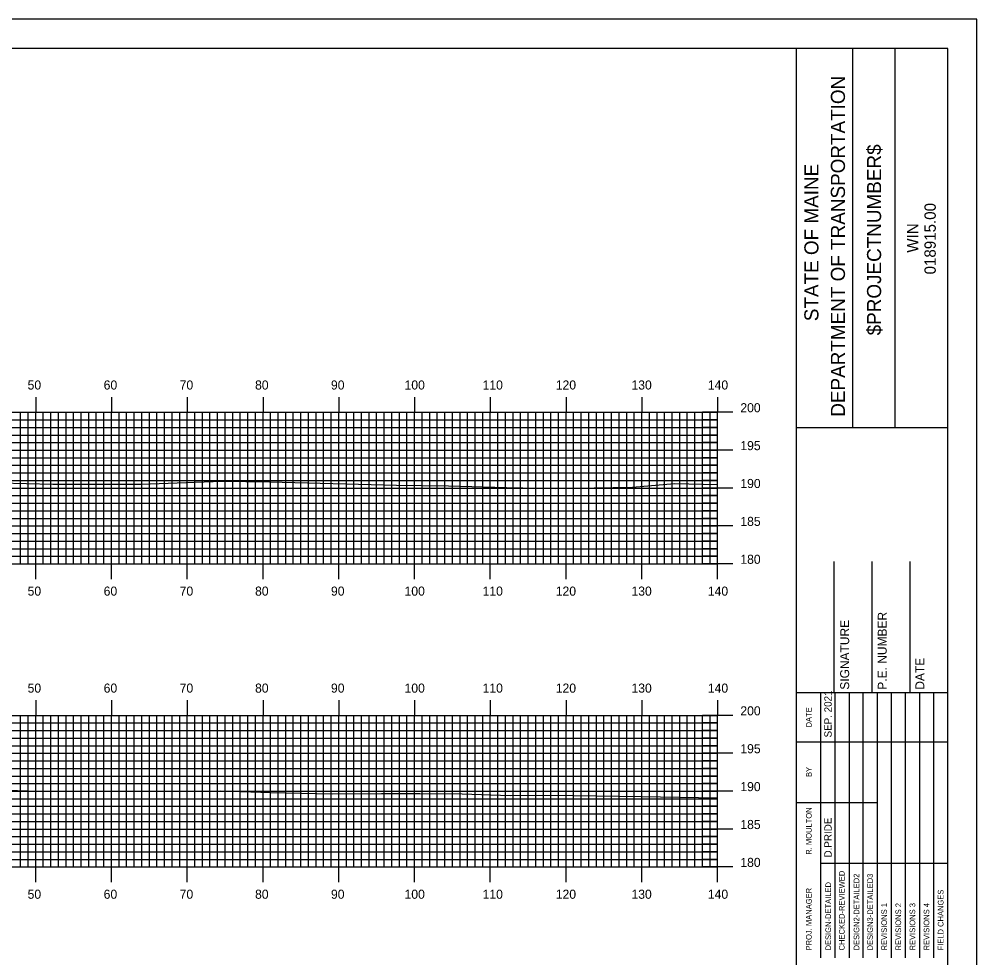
# Model space of a CAD drawing. Extents: x 1798388 to 1798731, y 442591 to 442811.
# Drawn here: x 1798601.3 to 1798727.7, y 442686.7 to 442810.5 of the extents above; entities that cross this region are included whole.
import ezdxf

# ---------------------------------------------------------------- set-up
doc = ezdxf.new("R2010")
doc.units = 0
for name, color, linetype in [('BORDER', 7, 'Continuous'), ('H_V ANNOTATION', 7, 'Continuous'), ('MAJOR', 7, 'Continuous'), ('MINOR', 7, 'Continuous'), ('PLOT BOUNDARY', 7, 'Continuous'), ('S_Roadway_Centerline', 7, 'Continuous')]:
    doc.layers.add(name, color=color, linetype=linetype)

msp = doc.modelspace()

# ---------------------------------------------------------------- linework, layer by layer
at = {"layer": 'BORDER'}
for p, q in [((1798703.87, 442596.67), (1798703.87, 442806.67)), ((1798711.33, 442756.66), (1798711.33, 442806.66)), ((1798716.92, 442756.66), (1798716.92, 442806.66)), ((1798703.87, 442756.65), (1798723.87, 442756.65)), ((1798708.87, 442721.67), (1798708.87, 442738.97)), ((1798713.87, 442721.67), (1798713.87, 442738.97)), ((1798718.87, 442721.67), (1798718.87, 442738.97)), ((1798703.87, 442721.67), (1798723.87, 442721.67))]:
    msp.add_line(p, q, dxfattribs=at)
msp.add_lwpolyline([(1798403.87, 442596.67), (1798723.87, 442596.67), (1798723.87, 442806.67), (1798403.87, 442806.67)], close=True, dxfattribs=at)
for points in [[(1798707.1, 442715.17), (1798707.1, 442721.67)], [(1798708.97, 442686.68), (1798708.97, 442721.67)], [(1798710.83, 442721.67), (1798710.83, 442686.68)], [(1798712.69, 442686.68), (1798712.69, 442721.67)], [(1798714.56, 442686.68), (1798714.56, 442721.67)], [(1798716.42, 442686.68), (1798716.42, 442721.67)], [(1798718.28, 442686.68), (1798718.28, 442721.67)], [(1798720.15, 442686.68), (1798720.15, 442721.67)], [(1798722.01, 442686.68), (1798722.01, 442721.67)], [(1798707.1, 442686.68), (1798707.1, 442720.26)], [(1798703.87, 442715.17), (1798723.87, 442715.17)], [(1798703.87, 442707.17), (1798707.1, 442707.17)], [(1798707.1, 442707.17), (1798714.55, 442707.17)], [(1798707.1, 442699.17), (1798723.87, 442699.17)]]:
    msp.add_lwpolyline(points, dxfattribs=at)
at = {"layer": 'MAJOR'}
for p, q in [((1798603.47, 442760.67), (1798603.47, 442758.67)), ((1798613.47, 442760.67), (1798613.47, 442758.67)), ((1798623.47, 442760.67), (1798623.47, 442758.67)), ((1798633.47, 442760.67), (1798633.47, 442758.67)), ((1798643.47, 442760.67), (1798643.47, 442758.67)), ((1798653.47, 442760.67), (1798653.47, 442758.67)), ((1798663.47, 442760.67), (1798663.47, 442758.67)), ((1798673.47, 442760.67), (1798673.47, 442758.67)), ((1798683.47, 442760.67), (1798683.47, 442758.67)), ((1798693.47, 442760.67), (1798693.47, 442758.67)), ((1798413.47, 442758.67), (1798693.47, 442758.67)), ((1798413.47, 442758.67), (1798693.47, 442758.67)), ((1798603.47, 442738.67), (1798603.47, 442758.67)), ((1798613.47, 442738.67), (1798613.47, 442758.67)), ((1798623.47, 442738.67), (1798623.47, 442758.67)), ((1798633.47, 442738.67), (1798633.47, 442758.67)), ((1798643.47, 442738.67), (1798643.47, 442758.67)), ((1798653.47, 442738.67), (1798653.47, 442758.67)), ((1798663.47, 442738.67), (1798663.47, 442758.67)), ((1798673.47, 442738.67), (1798673.47, 442758.67)), ((1798683.47, 442738.67), (1798683.47, 442758.67)), ((1798695.47, 442758.67), (1798691.47, 442758.67)), ((1798693.47, 442738.67), (1798693.47, 442758.67)), ((1798693.47, 442738.67), (1798693.47, 442758.67)), ((1798413.47, 442753.67), (1798693.47, 442753.67)), ((1798695.47, 442753.67), (1798691.47, 442753.67)), ((1798413.47, 442748.67), (1798693.47, 442748.67)), ((1798695.47, 442748.67), (1798691.47, 442748.67)), ((1798413.47, 442743.67), (1798693.47, 442743.67)), ((1798695.47, 442743.67), (1798691.47, 442743.67)), ((1798413.47, 442738.67), (1798693.47, 442738.67)), ((1798413.47, 442738.67), (1798693.47, 442738.67)), ((1798603.47, 442736.66), (1798603.47, 442738.67)), ((1798613.47, 442736.66), (1798613.47, 442738.67)), ((1798623.47, 442736.66), (1798623.47, 442738.67)), ((1798633.47, 442736.66), (1798633.47, 442738.67)), ((1798643.47, 442736.66), (1798643.47, 442738.67)), ((1798653.47, 442736.66), (1798653.47, 442738.67)), ((1798663.47, 442736.66), (1798663.47, 442738.67)), ((1798673.47, 442736.66), (1798673.47, 442738.67)), ((1798683.47, 442736.66), (1798683.47, 442738.67)), ((1798695.47, 442738.67), (1798691.47, 442738.67)), ((1798693.47, 442736.66), (1798693.47, 442738.67)), ((1798603.47, 442720.67), (1798603.47, 442718.67)), ((1798613.47, 442720.67), (1798613.47, 442718.67)), ((1798623.47, 442720.67), (1798623.47, 442718.67)), ((1798633.47, 442720.67), (1798633.47, 442718.67)), ((1798643.47, 442720.67), (1798643.47, 442718.67)), ((1798653.47, 442720.67), (1798653.47, 442718.67)), ((1798663.47, 442720.67), (1798663.47, 442718.67)), ((1798673.47, 442720.67), (1798673.47, 442718.67)), ((1798683.47, 442720.67), (1798683.47, 442718.67)), ((1798693.47, 442720.67), (1798693.47, 442718.67)), ((1798413.47, 442718.67), (1798693.47, 442718.67)), ((1798413.47, 442718.67), (1798693.47, 442718.67)), ((1798603.47, 442698.67), (1798603.47, 442718.67)), ((1798613.47, 442698.67), (1798613.47, 442718.67)), ((1798623.47, 442698.67), (1798623.47, 442718.67)), ((1798633.47, 442698.67), (1798633.47, 442718.67)), ((1798643.47, 442698.67), (1798643.47, 442718.67)), ((1798653.47, 442698.67), (1798653.47, 442718.67)), ((1798663.47, 442698.67), (1798663.47, 442718.67)), ((1798673.47, 442698.67), (1798673.47, 442718.67)), ((1798683.47, 442698.67), (1798683.47, 442718.67)), ((1798695.47, 442718.67), (1798691.47, 442718.67)), ((1798693.47, 442698.67), (1798693.47, 442718.67)), ((1798693.47, 442698.67), (1798693.47, 442718.67)), ((1798413.47, 442713.67), (1798693.47, 442713.67)), ((1798695.47, 442713.67), (1798691.47, 442713.67)), ((1798413.47, 442708.67), (1798693.47, 442708.67)), ((1798695.47, 442708.67), (1798691.47, 442708.67)), ((1798413.47, 442703.67), (1798693.47, 442703.67)), ((1798695.47, 442703.67), (1798691.47, 442703.67)), ((1798413.47, 442698.67), (1798693.47, 442698.67)), ((1798413.47, 442698.67), (1798693.47, 442698.67)), ((1798603.47, 442696.66), (1798603.47, 442698.67)), ((1798613.47, 442696.66), (1798613.47, 442698.67)), ((1798623.47, 442696.66), (1798623.47, 442698.67)), ((1798633.47, 442696.66), (1798633.47, 442698.67)), ((1798643.47, 442696.66), (1798643.47, 442698.67)), ((1798653.47, 442696.66), (1798653.47, 442698.67)), ((1798663.47, 442696.66), (1798663.47, 442698.67)), ((1798673.47, 442696.66), (1798673.47, 442698.67)), ((1798683.47, 442696.66), (1798683.47, 442698.67)), ((1798695.47, 442698.67), (1798691.47, 442698.67)), ((1798693.47, 442696.66), (1798693.47, 442698.67))]:
    msp.add_line(p, q, dxfattribs=at)
at = {"layer": 'MINOR'}
for p, q in [((1798601.47, 442738.67), (1798601.47, 442758.67)), ((1798602.47, 442738.67), (1798602.47, 442758.67)), ((1798604.47, 442738.67), (1798604.47, 442758.67)), ((1798605.47, 442738.67), (1798605.47, 442758.67)), ((1798606.47, 442738.67), (1798606.47, 442758.67)), ((1798607.47, 442738.67), (1798607.47, 442758.67)), ((1798608.47, 442738.67), (1798608.47, 442758.67)), ((1798609.47, 442738.67), (1798609.47, 442758.67)), ((1798610.47, 442738.67), (1798610.47, 442758.67)), ((1798611.47, 442738.67), (1798611.47, 442758.67)), ((1798612.47, 442738.67), (1798612.47, 442758.67)), ((1798614.47, 442738.67), (1798614.47, 442758.67)), ((1798615.47, 442738.67), (1798615.47, 442758.67)), ((1798616.47, 442738.67), (1798616.47, 442758.67)), ((1798617.47, 442738.67), (1798617.47, 442758.67)), ((1798618.47, 442738.67), (1798618.47, 442758.67)), ((1798619.47, 442738.67), (1798619.47, 442758.67)), ((1798620.47, 442738.67), (1798620.47, 442758.67)), ((1798621.47, 442738.67), (1798621.47, 442758.67)), ((1798622.47, 442738.67), (1798622.47, 442758.67)), ((1798624.47, 442738.67), (1798624.47, 442758.67)), ((1798625.47, 442738.67), (1798625.47, 442758.67)), ((1798626.47, 442738.67), (1798626.47, 442758.67)), ((1798627.47, 442738.67), (1798627.47, 442758.67)), ((1798628.47, 442738.67), (1798628.47, 442758.67)), ((1798629.47, 442738.67), (1798629.47, 442758.67)), ((1798630.47, 442738.67), (1798630.47, 442758.67)), ((1798631.47, 442738.67), (1798631.47, 442758.67)), ((1798632.47, 442738.67), (1798632.47, 442758.67)), ((1798634.47, 442738.67), (1798634.47, 442758.67)), ((1798635.47, 442738.67), (1798635.47, 442758.67)), ((1798636.47, 442738.67), (1798636.47, 442758.67)), ((1798637.47, 442738.67), (1798637.47, 442758.67)), ((1798638.47, 442738.67), (1798638.47, 442758.67)), ((1798639.47, 442738.67), (1798639.47, 442758.67)), ((1798640.47, 442738.67), (1798640.47, 442758.67)), ((1798641.47, 442738.67), (1798641.47, 442758.67)), ((1798642.47, 442738.67), (1798642.47, 442758.67)), ((1798644.47, 442738.67), (1798644.47, 442758.67)), ((1798645.47, 442738.67), (1798645.47, 442758.67)), ((1798646.47, 442738.67), (1798646.47, 442758.67)), ((1798647.47, 442738.67), (1798647.47, 442758.67)), ((1798648.47, 442738.67), (1798648.47, 442758.67)), ((1798649.47, 442738.67), (1798649.47, 442758.67)), ((1798650.47, 442738.67), (1798650.47, 442758.67)), ((1798651.47, 442738.67), (1798651.47, 442758.67)), ((1798652.47, 442738.67), (1798652.47, 442758.67)), ((1798654.47, 442738.67), (1798654.47, 442758.67)), ((1798655.47, 442738.67), (1798655.47, 442758.67)), ((1798656.47, 442738.67), (1798656.47, 442758.67)), ((1798657.47, 442738.67), (1798657.47, 442758.67)), ((1798658.47, 442738.67), (1798658.47, 442758.67)), ((1798659.47, 442738.67), (1798659.47, 442758.67)), ((1798660.47, 442738.67), (1798660.47, 442758.67)), ((1798661.47, 442738.67), (1798661.47, 442758.67)), ((1798662.47, 442738.67), (1798662.47, 442758.67)), ((1798664.47, 442738.67), (1798664.47, 442758.67)), ((1798665.47, 442738.67), (1798665.47, 442758.67)), ((1798666.47, 442738.67), (1798666.47, 442758.67)), ((1798667.47, 442738.67), (1798667.47, 442758.67)), ((1798668.47, 442738.67), (1798668.47, 442758.67)), ((1798669.47, 442738.67), (1798669.47, 442758.67)), ((1798670.47, 442738.67), (1798670.47, 442758.67)), ((1798671.47, 442738.67), (1798671.47, 442758.67)), ((1798672.47, 442738.67), (1798672.47, 442758.67)), ((1798674.47, 442738.67), (1798674.47, 442758.67)), ((1798675.47, 442738.67), (1798675.47, 442758.67)), ((1798676.47, 442738.67), (1798676.47, 442758.67)), ((1798677.47, 442738.67), (1798677.47, 442758.67)), ((1798678.47, 442738.67), (1798678.47, 442758.67)), ((1798679.47, 442738.67), (1798679.47, 442758.67)), ((1798680.47, 442738.67), (1798680.47, 442758.67)), ((1798681.47, 442738.67), (1798681.47, 442758.67)), ((1798682.47, 442738.67), (1798682.47, 442758.67)), ((1798684.47, 442738.67), (1798684.47, 442758.67)), ((1798685.47, 442738.67), (1798685.47, 442758.67)), ((1798686.47, 442738.67), (1798686.47, 442758.67)), ((1798687.47, 442738.67), (1798687.47, 442758.67)), ((1798688.47, 442738.67), (1798688.47, 442758.67)), ((1798689.47, 442738.67), (1798689.47, 442758.67)), ((1798690.47, 442738.67), (1798690.47, 442758.67)), ((1798691.47, 442738.67), (1798691.47, 442758.67)), ((1798692.47, 442738.67), (1798692.47, 442758.67)), ((1798413.47, 442757.67), (1798693.47, 442757.67)), ((1798413.47, 442756.67), (1798693.47, 442756.67)), ((1798693.47, 442757.67), (1798691.47, 442757.67)), ((1798693.47, 442756.67), (1798691.47, 442756.67)), ((1798413.47, 442755.67), (1798693.47, 442755.67)), ((1798693.47, 442755.67), (1798691.47, 442755.67)), ((1798413.47, 442754.67), (1798693.47, 442754.67)), ((1798693.47, 442754.67), (1798691.47, 442754.67)), ((1798413.47, 442752.67), (1798693.47, 442752.67)), ((1798693.47, 442752.67), (1798691.47, 442752.67)), ((1798413.47, 442751.67), (1798693.47, 442751.67)), ((1798693.47, 442751.67), (1798691.47, 442751.67)), ((1798413.47, 442750.67), (1798693.47, 442750.67)), ((1798693.47, 442750.67), (1798691.47, 442750.67)), ((1798413.47, 442749.67), (1798693.47, 442749.67)), ((1798693.47, 442749.67), (1798691.47, 442749.67)), ((1798413.47, 442747.67), (1798693.47, 442747.67)), ((1798693.47, 442747.67), (1798691.47, 442747.67)), ((1798413.47, 442746.67), (1798693.47, 442746.67)), ((1798693.47, 442746.67), (1798691.47, 442746.67)), ((1798413.47, 442745.67), (1798693.47, 442745.67)), ((1798693.47, 442745.67), (1798691.47, 442745.67)), ((1798413.47, 442744.67), (1798693.47, 442744.67)), ((1798693.47, 442744.67), (1798691.47, 442744.67)), ((1798413.47, 442742.67), (1798693.47, 442742.67)), ((1798693.47, 442742.67), (1798691.47, 442742.67)), ((1798413.47, 442741.67), (1798693.47, 442741.67)), ((1798693.47, 442741.67), (1798691.47, 442741.67)), ((1798413.47, 442740.67), (1798693.47, 442740.67)), ((1798693.47, 442740.67), (1798691.47, 442740.67)), ((1798413.47, 442739.67), (1798693.47, 442739.67)), ((1798693.47, 442739.67), (1798691.47, 442739.67)), ((1798601.47, 442698.67), (1798601.47, 442718.67)), ((1798602.47, 442698.67), (1798602.47, 442718.67)), ((1798604.47, 442698.67), (1798604.47, 442718.67)), ((1798605.47, 442698.67), (1798605.47, 442718.67)), ((1798606.47, 442698.67), (1798606.47, 442718.67)), ((1798607.47, 442698.67), (1798607.47, 442718.67)), ((1798608.47, 442698.67), (1798608.47, 442718.67)), ((1798609.47, 442698.67), (1798609.47, 442718.67)), ((1798610.47, 442698.67), (1798610.47, 442718.67)), ((1798611.47, 442698.67), (1798611.47, 442718.67)), ((1798612.47, 442698.67), (1798612.47, 442718.67)), ((1798614.47, 442698.67), (1798614.47, 442718.67)), ((1798615.47, 442698.67), (1798615.47, 442718.67)), ((1798616.47, 442698.67), (1798616.47, 442718.67)), ((1798617.47, 442698.67), (1798617.47, 442718.67)), ((1798618.47, 442698.67), (1798618.47, 442718.67)), ((1798619.47, 442698.67), (1798619.47, 442718.67)), ((1798620.47, 442698.67), (1798620.47, 442718.67)), ((1798621.47, 442698.67), (1798621.47, 442718.67)), ((1798622.47, 442698.67), (1798622.47, 442718.67)), ((1798624.47, 442698.67), (1798624.47, 442718.67)), ((1798625.47, 442698.67), (1798625.47, 442718.67)), ((1798626.47, 442698.67), (1798626.47, 442718.67)), ((1798627.47, 442698.67), (1798627.47, 442718.67)), ((1798628.47, 442698.67), (1798628.47, 442718.67)), ((1798629.47, 442698.67), (1798629.47, 442718.67)), ((1798630.47, 442698.67), (1798630.47, 442718.67)), ((1798631.47, 442698.67), (1798631.47, 442718.67)), ((1798632.47, 442698.67), (1798632.47, 442718.67)), ((1798634.47, 442698.67), (1798634.47, 442718.67)), ((1798635.47, 442698.67), (1798635.47, 442718.67)), ((1798636.47, 442698.67), (1798636.47, 442718.67)), ((1798637.47, 442698.67), (1798637.47, 442718.67)), ((1798638.47, 442698.67), (1798638.47, 442718.67)), ((1798639.47, 442698.67), (1798639.47, 442718.67)), ((1798640.47, 442698.67), (1798640.47, 442718.67)), ((1798641.47, 442698.67), (1798641.47, 442718.67)), ((1798642.47, 442698.67), (1798642.47, 442718.67)), ((1798644.47, 442698.67), (1798644.47, 442718.67)), ((1798645.47, 442698.67), (1798645.47, 442718.67)), ((1798646.47, 442698.67), (1798646.47, 442718.67)), ((1798647.47, 442698.67), (1798647.47, 442718.67)), ((1798648.47, 442698.67), (1798648.47, 442718.67)), ((1798649.47, 442698.67), (1798649.47, 442718.67)), ((1798650.47, 442698.67), (1798650.47, 442718.67)), ((1798651.47, 442698.67), (1798651.47, 442718.67)), ((1798652.47, 442698.67), (1798652.47, 442718.67)), ((1798654.47, 442698.67), (1798654.47, 442718.67)), ((1798655.47, 442698.67), (1798655.47, 442718.67)), ((1798656.47, 442698.67), (1798656.47, 442718.67)), ((1798657.47, 442698.67), (1798657.47, 442718.67)), ((1798658.47, 442698.67), (1798658.47, 442718.67)), ((1798659.47, 442698.67), (1798659.47, 442718.67)), ((1798660.47, 442698.67), (1798660.47, 442718.67)), ((1798661.47, 442698.67), (1798661.47, 442718.67)), ((1798662.47, 442698.67), (1798662.47, 442718.67)), ((1798664.47, 442698.67), (1798664.47, 442718.67)), ((1798665.47, 442698.67), (1798665.47, 442718.67)), ((1798666.47, 442698.67), (1798666.47, 442718.67)), ((1798667.47, 442698.67), (1798667.47, 442718.67)), ((1798668.47, 442698.67), (1798668.47, 442718.67)), ((1798669.47, 442698.67), (1798669.47, 442718.67)), ((1798670.47, 442698.67), (1798670.47, 442718.67)), ((1798671.47, 442698.67), (1798671.47, 442718.67)), ((1798672.47, 442698.67), (1798672.47, 442718.67)), ((1798674.47, 442698.67), (1798674.47, 442718.67)), ((1798675.47, 442698.67), (1798675.47, 442718.67)), ((1798676.47, 442698.67), (1798676.47, 442718.67)), ((1798677.47, 442698.67), (1798677.47, 442718.67)), ((1798678.47, 442698.67), (1798678.47, 442718.67)), ((1798679.47, 442698.67), (1798679.47, 442718.67)), ((1798680.47, 442698.67), (1798680.47, 442718.67)), ((1798681.47, 442698.67), (1798681.47, 442718.67)), ((1798682.47, 442698.67), (1798682.47, 442718.67)), ((1798684.47, 442698.67), (1798684.47, 442718.67)), ((1798685.47, 442698.67), (1798685.47, 442718.67)), ((1798686.47, 442698.67), (1798686.47, 442718.67)), ((1798687.47, 442698.67), (1798687.47, 442718.67)), ((1798688.47, 442698.67), (1798688.47, 442718.67)), ((1798689.47, 442698.67), (1798689.47, 442718.67)), ((1798690.47, 442698.67), (1798690.47, 442718.67)), ((1798691.47, 442698.67), (1798691.47, 442718.67)), ((1798692.47, 442698.67), (1798692.47, 442718.67)), ((1798413.47, 442717.67), (1798693.47, 442717.67)), ((1798693.47, 442717.67), (1798691.47, 442717.67)), ((1798413.47, 442716.67), (1798693.47, 442716.67)), ((1798693.47, 442716.67), (1798691.47, 442716.67)), ((1798413.47, 442715.67), (1798693.47, 442715.67)), ((1798693.47, 442715.67), (1798691.47, 442715.67)), ((1798413.47, 442714.67), (1798693.47, 442714.67)), ((1798693.47, 442714.67), (1798691.47, 442714.67)), ((1798413.47, 442712.67), (1798693.47, 442712.67)), ((1798693.47, 442712.67), (1798691.47, 442712.67)), ((1798413.47, 442711.67), (1798693.47, 442711.67)), ((1798693.47, 442711.67), (1798691.47, 442711.67)), ((1798413.47, 442710.67), (1798693.47, 442710.67)), ((1798413.47, 442709.67), (1798693.47, 442709.67)), ((1798693.47, 442710.67), (1798691.47, 442710.67)), ((1798693.47, 442709.67), (1798691.47, 442709.67)), ((1798413.47, 442707.67), (1798693.47, 442707.67)), ((1798693.47, 442707.67), (1798691.47, 442707.67)), ((1798413.47, 442706.67), (1798693.47, 442706.67)), ((1798693.47, 442706.67), (1798691.47, 442706.67)), ((1798413.47, 442705.67), (1798693.47, 442705.67)), ((1798413.47, 442704.67), (1798693.47, 442704.67)), ((1798693.47, 442705.67), (1798691.47, 442705.67)), ((1798693.47, 442704.67), (1798691.47, 442704.67)), ((1798413.47, 442702.67), (1798693.47, 442702.67)), ((1798693.47, 442702.67), (1798691.47, 442702.67)), ((1798413.47, 442701.67), (1798693.47, 442701.67)), ((1798693.47, 442701.67), (1798691.47, 442701.67)), ((1798413.47, 442700.67), (1798693.47, 442700.67)), ((1798413.47, 442699.67), (1798693.47, 442699.67)), ((1798693.47, 442700.67), (1798691.47, 442700.67)), ((1798693.47, 442699.67), (1798691.47, 442699.67))]:
    msp.add_line(p, q, dxfattribs=at)
at = {"layer": 'PLOT BOUNDARY'}
msp.add_lwpolyline([(1798387.68, 442590.55), (1798727.68, 442590.55), (1798727.68, 442810.55), (1798387.68, 442810.55)], close=True, dxfattribs=at)
at = {"layer": 'S_Roadway_Centerline'}
for points in [[(1798598.75, 442749.36), (1798605.74, 442749.2), (1798617.38, 442749.17), (1798628.09, 442749.56), (1798634.33, 442749.47), (1798651.07, 442749.06), (1798657.94, 442748.98), (1798665.61, 442748.75), (1798672.06, 442748.59), (1798682.23, 442748.8), (1798687.8, 442749.26), (1798693.47, 442749.13)], [(1798586.14, 442709.19), (1798605.51, 442708.63), (1798610.85, 442708.69), (1798627.88, 442708.71), (1798634.49, 442708.49), (1798642.58, 442708.31), (1798649.09, 442708.38), (1798654.15, 442708.35), (1798659.77, 442708.33), (1798666.09, 442708.11), (1798671.42, 442708.16), (1798683.44, 442707.95), (1798693.47, 442707.78)]]:
    msp.add_lwpolyline(points, dxfattribs=at)

# ---------------------------------------------------------------- texts
at = {"layer": 'BORDER'}
for s, height, p in [('DEPARTMENT OF TRANSPORTATION', 1.8635, (1798710.28, 442758.08)), ('$PROJECTNUMBER$', 1.8635, (1798715.05, 442768.82)), ('STATE OF MAINE', 1.8635, (1798706.78, 442770.69)), ('018915.00', 1.491, (1798722.26, 442776.86)), ('WIN', 1.491, (1798719.94, 442779.73)), ('SIGNATURE', 1.181, (1798710.83, 442722.06)), ('P.E. NUMBER', 1.1811, (1798715.79, 442722.06)), ('DATE', 1.181, (1798720.75, 442722.06)), ('SEP. 2021', 0.969, (1798708.52, 442715.76)), ('DATE', 0.743, (1798705.88, 442717.08)), ('BY', 0.743, (1798705.88, 442710.54)), ('R. MOULTON', 0.745, (1798705.88, 442700.28)), ('D.PRIDE', 0.969, (1798708.52, 442699.92)), ('CHECKED-REVIEWED', 0.7455, (1798710.23, 442687.65)), ('DESIGN2-DETAILED2', 0.7455, (1798712.17, 442687.65)), ('DESIGN3-DETAILED3', 0.7455, (1798713.96, 442687.65)), ('PROJ. MANAGER', 0.7455, (1798705.88, 442687.65)), ('DESIGN-DETAILED', 0.7455, (1798708.44, 442687.65)), ('FIELD CHANGES', 0.7455, (1798723.28, 442687.65)), ('REVISIONS 1', 0.7455, (1798715.82, 442687.65)), ('REVISIONS 2', 0.7455, (1798717.69, 442687.65)), ('REVISIONS 3', 0.7455, (1798719.55, 442687.65)), ('REVISIONS 4', 0.7455, (1798721.41, 442687.65))]:
    msp.add_text(s, height=height, rotation=90, dxfattribs=at).set_placement(p)
at = {"layer": 'H_V ANNOTATION'}
for s, p in [('50', (1798602.4, 442761.67)), ('60', (1798612.44, 442761.67)), ('70', (1798622.47, 442761.67)), ('80', (1798632.42, 442761.67)), ('90', (1798642.44, 442761.67)), ('100', (1798652.15, 442761.67)), ('110', (1798662.45, 442761.67)), ('120', (1798672.11, 442761.67)), ('130', (1798682.1, 442761.67)), ('140', (1798692.18, 442761.67)), ('200', (1798696.47, 442758.67)), ('195', (1798696.47, 442753.67)), ('190', (1798696.47, 442748.67)), ('185', (1798696.47, 442743.67)), ('180', (1798696.47, 442738.67)), ('50', (1798602.4, 442734.47)), ('60', (1798612.44, 442734.47)), ('70', (1798622.47, 442734.47)), ('80', (1798632.42, 442734.47)), ('90', (1798642.44, 442734.47)), ('100', (1798652.15, 442734.47)), ('110', (1798662.45, 442734.47)), ('120', (1798672.11, 442734.47)), ('130', (1798682.1, 442734.47)), ('140', (1798692.18, 442734.47)), ('50', (1798602.4, 442721.67)), ('60', (1798612.44, 442721.67)), ('70', (1798622.47, 442721.67)), ('80', (1798632.42, 442721.67)), ('90', (1798642.44, 442721.67)), ('100', (1798652.15, 442721.67)), ('110', (1798662.45, 442721.67)), ('120', (1798672.11, 442721.67)), ('130', (1798682.1, 442721.67)), ('140', (1798692.18, 442721.67)), ('200', (1798696.47, 442718.67)), ('195', (1798696.47, 442713.67)), ('190', (1798696.47, 442708.67)), ('185', (1798696.47, 442703.67)), ('180', (1798696.47, 442698.67)), ('50', (1798602.4, 442694.47)), ('60', (1798612.44, 442694.47)), ('70', (1798622.47, 442694.47)), ('80', (1798632.42, 442694.47)), ('90', (1798642.44, 442694.47)), ('100', (1798652.15, 442694.47)), ('110', (1798662.45, 442694.47)), ('120', (1798672.11, 442694.47)), ('130', (1798682.1, 442694.47)), ('140', (1798692.18, 442694.47))]:
    msp.add_text(s, height=1.2, dxfattribs=at).set_placement(p)

doc.saveas('drawing.dxf')
